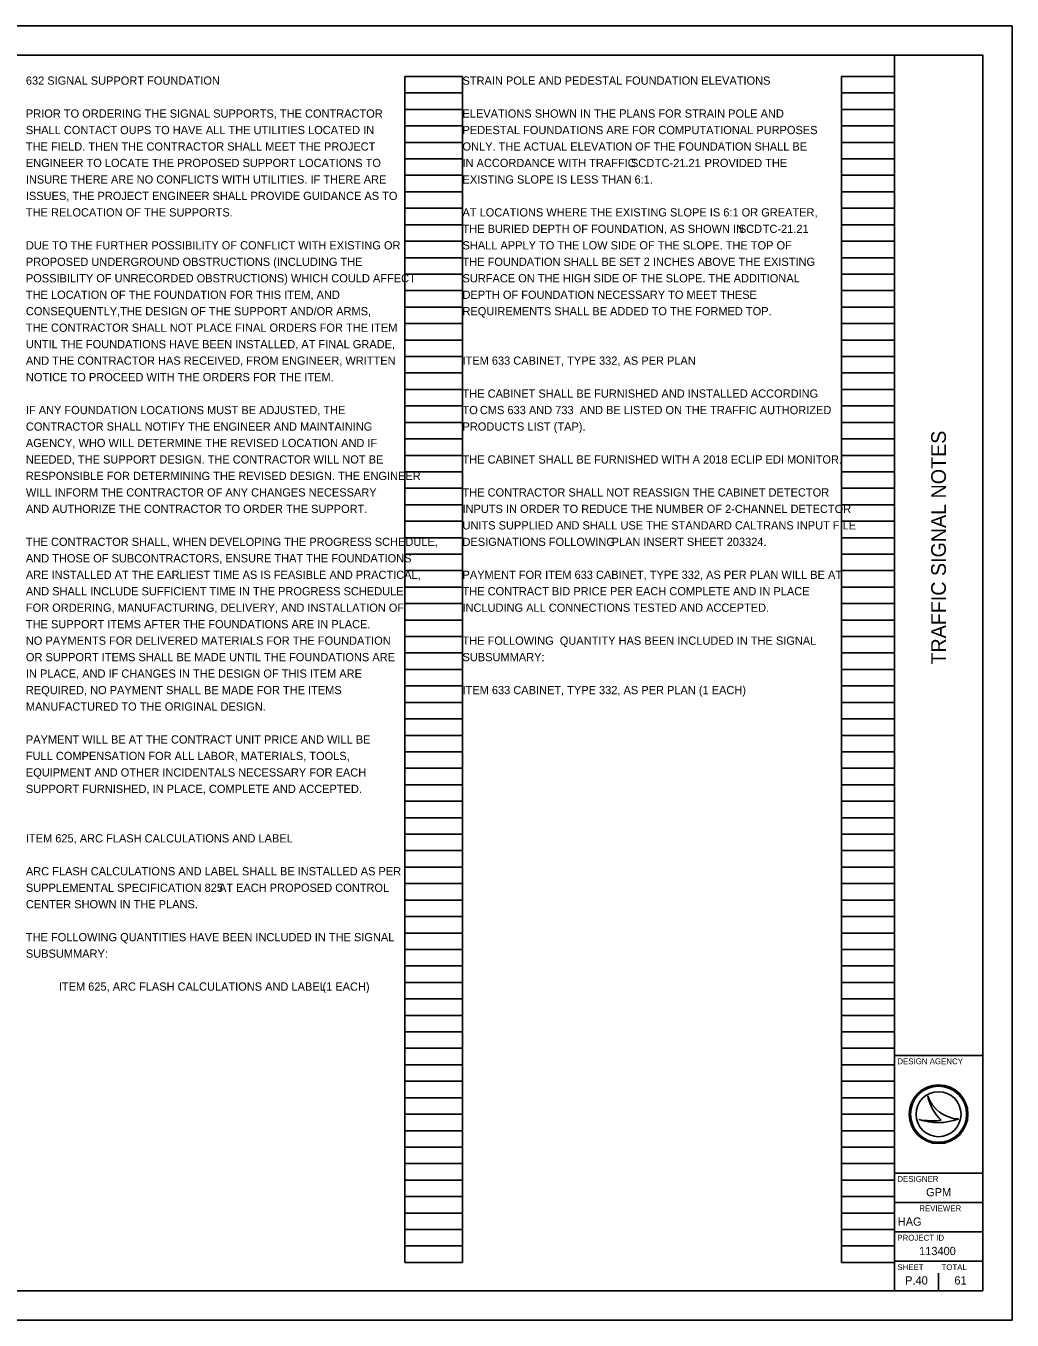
# Model space of a CAD drawing. Extents: x 0 to 34, y 0 to 22.
# Drawn here: x 17.24 to 34, y 0 to 22 of the extents above; entities that cross this region are included whole.
import ezdxf

# ---------------------------------------------------------------- set-up
doc = ezdxf.new("R2010")
doc.units = 0
for name, color, linetype in [('SH_Border', 7, 'Continuous'), ('SH_Cut_Line', 7, 'Continuous'), ('SH_Data', 7, 'Continuous'), ('SH_Text', 7, 'Continuous')]:
    doc.layers.add(name, color=color, linetype=linetype)

msp = doc.modelspace()

# ---------------------------------------------------------------- linework, layer by layer
at = {"layer": 'SH_Border'}
for p, q in [((32, 0.5), (32, 21.5)), ((32, 4.5), (33.5, 4.5)), ((32, 2.5), (33.5, 2.5)), ((32, 2), (33.5, 2)), ((32, 1.5), (33.5, 1.5)), ((32, 1), (33.5, 1))]:
    msp.add_line(p, q, dxfattribs=at)
msp.add_lwpolyline([(1.5, 21.5), (33.5, 21.5), (33.5, 0.5), (1.5, 0.5)], close=True, dxfattribs=at)
at = {"layer": 'SH_Cut_Line'}
msp.add_lwpolyline([(0, 0), (34, 0), (34, 22), (0, 22)], close=True, dxfattribs=at)
at = {"layer": 'SH_Data'}
for p, q in [((23.68, 0.98), (23.68, 21.14)), ((23.68, 21.14), (24.66, 21.14)), ((24.66, 0.98), (24.66, 21.14)), ((31.1, 0.98), (31.1, 21.14)), ((31.1, 21.14), (32, 21.14)), ((32, 0.98), (32, 21.14)), ((23.68, 20.86), (24.66, 20.86)), ((31.1, 20.86), (32, 20.86)), ((23.68, 20.58), (24.66, 20.58)), ((31.1, 20.58), (32, 20.58)), ((23.68, 20.3), (24.66, 20.3)), ((31.1, 20.3), (32, 20.3)), ((23.68, 20.02), (24.66, 20.02)), ((31.1, 20.02), (32, 20.02)), ((23.68, 19.74), (24.66, 19.74)), ((31.1, 19.74), (32, 19.74)), ((23.68, 19.46), (24.66, 19.46)), ((31.1, 19.46), (32, 19.46)), ((23.68, 19.18), (24.66, 19.18)), ((31.1, 19.18), (32, 19.18)), ((23.68, 18.9), (24.66, 18.9)), ((31.1, 18.9), (32, 18.9)), ((23.68, 18.62), (24.66, 18.62)), ((31.1, 18.62), (32, 18.62)), ((23.68, 18.34), (24.66, 18.34)), ((31.1, 18.34), (32, 18.34)), ((23.68, 18.06), (24.66, 18.06)), ((31.1, 18.06), (32, 18.06)), ((23.68, 17.78), (24.66, 17.78)), ((31.1, 17.78), (32, 17.78)), ((23.68, 17.5), (24.66, 17.5)), ((31.1, 17.5), (32, 17.5)), ((23.68, 17.22), (24.66, 17.22)), ((31.1, 17.22), (32, 17.22)), ((23.68, 16.94), (24.66, 16.94)), ((31.1, 16.94), (32, 16.94)), ((23.68, 16.66), (24.66, 16.66)), ((31.1, 16.66), (32, 16.66)), ((23.68, 16.38), (24.66, 16.38)), ((31.1, 16.38), (32, 16.38)), ((23.68, 16.1), (24.66, 16.1)), ((31.1, 16.1), (32, 16.1)), ((23.68, 15.82), (24.66, 15.82)), ((31.1, 15.82), (32, 15.82)), ((23.68, 15.54), (24.66, 15.54)), ((31.1, 15.54), (32, 15.54)), ((23.68, 15.26), (24.66, 15.26)), ((31.1, 15.26), (32, 15.26)), ((23.68, 14.98), (24.66, 14.98)), ((31.1, 14.98), (32, 14.98)), ((23.68, 14.7), (24.66, 14.7)), ((31.1, 14.7), (32, 14.7)), ((23.68, 14.42), (24.66, 14.42)), ((31.1, 14.42), (32, 14.42)), ((23.68, 14.14), (24.66, 14.14)), ((31.1, 14.14), (32, 14.14)), ((23.68, 13.86), (24.66, 13.86)), ((31.1, 13.86), (32, 13.86)), ((23.68, 13.58), (24.66, 13.58)), ((31.1, 13.58), (32, 13.58)), ((23.68, 13.3), (24.66, 13.3)), ((31.1, 13.3), (32, 13.3)), ((23.68, 13.02), (24.66, 13.02)), ((31.1, 13.02), (32, 13.02)), ((23.68, 12.74), (24.66, 12.74)), ((31.1, 12.74), (32, 12.74)), ((23.68, 12.46), (24.66, 12.46)), ((31.1, 12.46), (32, 12.46)), ((23.68, 12.18), (24.66, 12.18)), ((31.1, 12.18), (32, 12.18)), ((23.68, 11.9), (24.66, 11.9)), ((31.1, 11.9), (32, 11.9)), ((23.68, 11.62), (24.66, 11.62)), ((31.1, 11.62), (32, 11.62)), ((23.68, 11.34), (24.66, 11.34)), ((31.1, 11.34), (32, 11.34)), ((23.68, 11.06), (24.66, 11.06)), ((31.1, 11.06), (32, 11.06)), ((23.68, 10.78), (24.66, 10.78)), ((31.1, 10.78), (32, 10.78)), ((23.68, 10.5), (24.66, 10.5)), ((31.1, 10.5), (32, 10.5)), ((23.68, 10.22), (24.66, 10.22)), ((31.1, 10.22), (32, 10.22)), ((23.68, 9.94), (24.66, 9.94)), ((31.1, 9.94), (32, 9.94)), ((23.68, 9.66), (24.66, 9.66)), ((31.1, 9.66), (32, 9.66)), ((23.68, 9.38), (24.66, 9.38)), ((31.1, 9.38), (32, 9.38)), ((23.68, 9.1), (24.66, 9.1)), ((31.1, 9.1), (32, 9.1)), ((23.68, 8.82), (24.66, 8.82)), ((31.1, 8.82), (32, 8.82)), ((23.68, 8.54), (24.66, 8.54)), ((31.1, 8.54), (32, 8.54)), ((23.68, 8.26), (24.66, 8.26)), ((31.1, 8.26), (32, 8.26)), ((23.68, 7.98), (24.66, 7.98)), ((31.1, 7.98), (32, 7.98)), ((23.68, 7.7), (24.66, 7.7)), ((31.1, 7.7), (32, 7.7)), ((23.68, 7.42), (24.66, 7.42)), ((31.1, 7.42), (32, 7.42)), ((23.68, 7.14), (24.66, 7.14)), ((31.1, 7.14), (32, 7.14)), ((23.68, 6.86), (24.66, 6.86)), ((31.1, 6.86), (32, 6.86)), ((23.68, 6.58), (24.66, 6.58)), ((31.1, 6.58), (32, 6.58)), ((23.68, 6.3), (24.66, 6.3)), ((31.1, 6.3), (32, 6.3)), ((23.68, 6.02), (24.66, 6.02)), ((31.1, 6.02), (32, 6.02)), ((23.68, 5.74), (24.66, 5.74)), ((31.1, 5.74), (32, 5.74)), ((23.68, 5.46), (24.66, 5.46)), ((31.1, 5.46), (32, 5.46)), ((23.68, 5.18), (24.66, 5.18)), ((31.1, 5.18), (32, 5.18)), ((23.68, 4.9), (24.66, 4.9)), ((31.1, 4.9), (32, 4.9)), ((23.68, 4.62), (24.66, 4.62)), ((31.1, 4.62), (32, 4.62)), ((23.68, 4.34), (24.66, 4.34)), ((31.1, 4.34), (32, 4.34)), ((23.68, 4.06), (24.66, 4.06)), ((31.1, 4.06), (32, 4.06)), ((23.68, 3.78), (24.66, 3.78)), ((31.1, 3.78), (32, 3.78)), ((32.567, 3.81), (32.567, 3.81)), ((23.68, 3.5), (24.66, 3.5)), ((31.1, 3.5), (32, 3.5)), ((32.417, 3.41), (32.417, 3.41)), ((32.75, 3.5), (32.75, 3.5)), ((33.087, 3.419), (33.087, 3.419)), ((23.68, 3.22), (24.66, 3.22)), ((31.1, 3.22), (32, 3.22)), ((23.68, 2.94), (24.66, 2.94)), ((31.1, 2.94), (32, 2.94)), ((23.68, 2.66), (24.66, 2.66)), ((31.1, 2.66), (32, 2.66)), ((23.68, 2.38), (24.66, 2.38)), ((31.1, 2.38), (32, 2.38)), ((23.68, 2.1), (24.66, 2.1)), ((31.1, 2.1), (32, 2.1)), ((23.68, 1.82), (24.66, 1.82)), ((31.1, 1.82), (32, 1.82)), ((23.68, 1.54), (24.66, 1.54)), ((31.1, 1.54), (32, 1.54)), ((23.68, 1.26), (24.66, 1.26)), ((31.1, 1.26), (32, 1.26)), ((23.68, 0.98), (24.66, 0.98)), ((31.1, 0.98), (32, 0.98)), ((32.375, 0.675), (32.375, 0.675)), ((32.75, 0.5), (32.75, 0.8))]:
    msp.add_line(p, q, dxfattribs=at)
for radius in [0.5, 0.477, 0.477, 0.382]:
    msp.add_circle((32.75, 3.5), radius, dxfattribs=at)
for centre, radius, start, end in [((33.116, 3.998), 0.58, 198.9257, 198.9319), ((33.347, 3.97), 0.796, 191.6379, 191.6421), ((33.116, 3.998), 0.58, 198.9319, 267.1657), ((33.347, 3.97), 0.796, 191.6421, 226.0947), ((32.739, 4.37), 1.013, 251.4576, 290.0832), ((32.648, 4.654), 1.266, 259.4964, 259.4995), ((32.739, 4.37), 1.013, 251.4527, 251.4576), ((32.648, 4.654), 1.266, 259.4995, 276.6672)]:
    msp.add_arc(centre, radius, start, end, dxfattribs=at)

# ---------------------------------------------------------------- texts
msp.add_text('TRAFFIC SIGNAL NOTES', height=0.25, rotation=90, dxfattribs=at).set_placement((32.875, 11.144))
for s, height, p in [('DESIGN AGENCY', 0.1, (32.05, 4.35)), ('DESIGNER', 0.1, (32.05, 2.35)), ('GPM', 0.14, (32.538, 2.105)), ('REVIEWER', 0.1, (32.422, 1.85)), ('HAG', 0.14, (32.057, 1.605)), ('PROJECT ID', 0.1, (32.05, 1.35)), ('113400', 0.14, (32.419, 1.105)), ('SHEET', 0.1, (32.05, 0.85)), ('TOTAL', 0.1, (32.8, 0.85)), ('P.40', 0.14, (32.182, 0.605)), ('61', 0.14, (33.019, 0.605))]:
    msp.add_text(s, height=height, dxfattribs=at).set_placement(p)
at = {"layer": 'SH_Text'}
for s, p in [('632 SIGNAL SUPPORT FOUNDATION', (17.24, 21)), ('STRAIN POLE AND PEDESTAL FOUNDATION ELEVATIONS', (24.66, 21)), ('PRIOR TO ORDERING THE SIGNAL SUPPORTS, THE CONTRACTOR', (17.24, 20.44)), ('ELEVATIONS SHOWN IN THE PLANS FOR STRAIN POLE AND', (24.66, 20.44)), ('SHALL CONTACT OUPS TO HAVE ALL THE UTILITIES LOCATED IN', (17.24, 20.16)), ('PEDESTAL FOUNDATIONS ARE FOR COMPUTATIONAL PURPOSES', (24.66, 20.16)), ('THE FIELD. THEN THE CONTRACTOR SHALL MEET THE PROJECT', (17.24, 19.88)), ('ONLY. THE ACTUAL ELEVATION OF THE FOUNDATION SHALL BE', (24.66, 19.88)), ('ENGINEER TO LOCATE THE PROPOSED SUPPORT LOCATIONS TO', (17.24, 19.6)), ('IN ACCORDANCE WITH TRAFFIC ', (24.66, 19.6)), ('SCD', (27.523, 19.6)), ('TC-21.21', (27.929, 19.6)), (' PROVIDED THE', (28.722, 19.6)), ('INSURE THERE ARE NO CONFLICTS WITH UTILITIES. IF THERE ARE', (17.24, 19.32)), ('EXISTING SLOPE IS LESS THAN 6:1.', (24.66, 19.32)), ('ISSUES, THE PROJECT ENGINEER SHALL PROVIDE GUIDANCE AS TO', (17.24, 19.04)), ('THE RELOCATION OF THE SUPPORTS.', (17.24, 18.76)), ('AT LOCATIONS WHERE THE EXISTING SLOPE IS 6:1 OR GREATER,', (24.66, 18.76)), ('THE BURIED DEPTH OF FOUNDATION, AS SHOWN IN ', (24.66, 18.48)), ('SCD', (29.356, 18.48)), ('TC-21.21', (29.762, 18.48)), ('DUE TO THE FURTHER POSSIBILITY OF CONFLICT WITH EXISTING OR', (17.24, 18.2)), ('SHALL APPLY TO THE LOW SIDE OF THE SLOPE. THE TOP OF', (24.66, 18.2)), ('PROPOSED UNDERGROUND OBSTRUCTIONS (INCLUDING THE', (17.24, 17.92)), ('THE FOUNDATION SHALL BE SET 2 INCHES ABOVE THE EXISTING', (24.66, 17.92)), ('POSSIBILITY OF UNRECORDED OBSTRUCTIONS) WHICH COULD AFFECT ', (17.24, 17.64)), ('SURFACE ON THE HIGH SIDE OF THE SLOPE. THE ADDITIONAL', (24.66, 17.64)), ('THE LOCATION OF THE FOUNDATION FOR THIS ITEM, AND', (17.24, 17.36)), ('DEPTH OF FOUNDATION NECESSARY TO MEET THESE', (24.66, 17.36)), ('CONSEQUENTLY,THE DESIGN OF THE SUPPORT AND/OR ARMS,', (17.24, 17.08)), ('REQUIREMENTS SHALL BE ADDED TO THE FORMED TOP.', (24.66, 17.08)), ('THE CONTRACTOR SHALL NOT PLACE FINAL ORDERS FOR THE ITEM', (17.24, 16.8)), ('UNTIL THE FOUNDATIONS HAVE BEEN INSTALLED, AT FINAL GRADE,', (17.24, 16.52)), ('AND THE CONTRACTOR HAS RECEIVED, FROM ENGINEER, WRITTEN', (17.24, 16.24)), ('ITEM 633 CABINET, TYPE 332, AS PER PLAN', (24.66, 16.24)), ('NOTICE TO PROCEED WITH THE ORDERS FOR THE ITEM.', (17.24, 15.96)), ('THE CABINET SHALL BE FURNISHED AND INSTALLED ACCORDING', (24.66, 15.68)), ('IF ANY FOUNDATION LOCATIONS MUST BE ADJUSTED, THE', (17.24, 15.4)), ('TO ', (24.66, 15.4)), ('CMS 633 AND 733 ', (24.956, 15.4)), ('AND BE LISTED ON THE TRAFFIC AUTHORIZED', (26.653, 15.4)), ('CONTRACTOR SHALL NOTIFY THE ENGINEER AND MAINTAINING', (17.24, 15.12)), ('PRODUCTS LIST (TAP).', (24.66, 15.12)), ('AGENCY, WHO WILL DETERMINE THE REVISED LOCATION AND IF', (17.24, 14.84)), ('NEEDED, THE SUPPORT DESIGN. THE CONTRACTOR WILL NOT BE ', (17.24, 14.56)), ('THE CABINET SHALL BE FURNISHED WITH A 2018 ECLIP EDI MONITOR.', (24.66, 14.56)), ('RESPONSIBLE FOR DETERMINING THE REVISED DESIGN. THE ENGINEER', (17.24, 14.28)), ('WILL INFORM THE CONTRACTOR OF ANY CHANGES NECESSARY', (17.24, 14)), ('THE CONTRACTOR SHALL NOT REASSIGN THE CABINET DETECTOR', (24.66, 14)), ('AND AUTHORIZE THE CONTRACTOR TO ORDER THE SUPPORT.', (17.24, 13.72)), ('INPUTS IN ORDER TO REDUCE THE NUMBER OF 2-CHANNEL DETECTOR', (24.66, 13.72)), ('UNITS SUPPLIED AND SHALL USE THE STANDARD CALTRANS INPUT FILE', (24.66, 13.44)), ('THE CONTRACTOR SHALL, WHEN DEVELOPING THE PROGRESS SCHEDULE,', (17.24, 13.16)), ('DESIGNATIONS FOLLOWING ', (24.66, 13.16)), ('PLAN INSERT SHEET 203324. ', (27.194, 13.16)), ('AND THOSE OF SUBCONTRACTORS, ENSURE THAT THE FOUNDATIONS', (17.24, 12.88)), ('ARE INSTALLED AT THE EARLIEST TIME AS IS FEASIBLE AND PRACTICAL,', (17.24, 12.6)), ('PAYMENT FOR ITEM 633 CABINET, TYPE 332, AS PER PLAN WILL BE AT', (24.66, 12.6)), ('AND SHALL INCLUDE SUFFICIENT TIME IN THE PROGRESS SCHEDULE', (17.24, 12.32)), ('THE CONTRACT BID PRICE PER EACH COMPLETE AND IN PLACE', (24.66, 12.32)), ('FOR ORDERING, MANUFACTURING, DELIVERY, AND INSTALLATION OF', (17.24, 12.04)), ('INCLUDING ALL CONNECTIONS TESTED AND ACCEPTED.', (24.66, 12.04)), ('THE SUPPORT ITEMS AFTER THE FOUNDATIONS ARE IN PLACE.', (17.24, 11.76)), ('NO PAYMENTS FOR DELIVERED MATERIALS FOR THE FOUNDATION', (17.24, 11.48)), ('THE FOLLOWING  QUANTITY HAS BEEN INCLUDED IN THE SIGNAL', (24.66, 11.48)), ('OR SUPPORT ITEMS SHALL BE MADE UNTIL THE FOUNDATIONS ARE', (17.24, 11.2)), ('SUBSUMMARY:', (24.66, 11.2)), ('IN PLACE, AND IF CHANGES IN THE DESIGN OF THIS ITEM ARE', (17.24, 10.92)), ('REQUIRED, NO PAYMENT SHALL BE MADE FOR THE ITEMS', (17.24, 10.64)), ('ITEM 633 CABINET, TYPE 332, AS PER PLAN (1 EACH)', (24.66, 10.64)), ('MANUFACTURED TO THE ORIGINAL DESIGN.', (17.24, 10.36)), ('PAYMENT WILL BE AT THE CONTRACT UNIT PRICE AND WILL BE', (17.24, 9.8)), ('FULL COMPENSATION FOR ALL LABOR, MATERIALS, TOOLS,', (17.24, 9.52)), ('EQUIPMENT AND OTHER INCIDENTALS NECESSARY FOR EACH', (17.24, 9.24)), ('SUPPORT FURNISHED, IN PLACE, COMPLETE AND ACCEPTED.', (17.24, 8.96)), ('ITEM 625, ARC FLASH CALCULATIONS AND LABEL', (17.24, 8.12)), ('ARC FLASH CALCULATIONS AND LABEL SHALL BE INSTALLED AS PER', (17.24, 7.56)), ('SUPPLEMENTAL SPECIFICATION 825 ', (17.24, 7.28)), ('AT EACH PROPOSED CONTROL', (20.521, 7.28)), ('CENTER SHOWN IN THE PLANS.', (17.24, 7)), ('THE FOLLOWING QUANTITIES HAVE BEEN INCLUDED IN THE SIGNAL', (17.24, 6.44)), ('SUBSUMMARY:', (17.24, 6.16)), ('ITEM 625, ARC FLASH CALCULATIONS AND LABEL', (17.8, 5.6)), ('(1 EACH)', (22.28, 5.6))]:
    msp.add_text(s, height=0.14, dxfattribs=at).set_placement(p)

doc.saveas('drawing.dxf')
